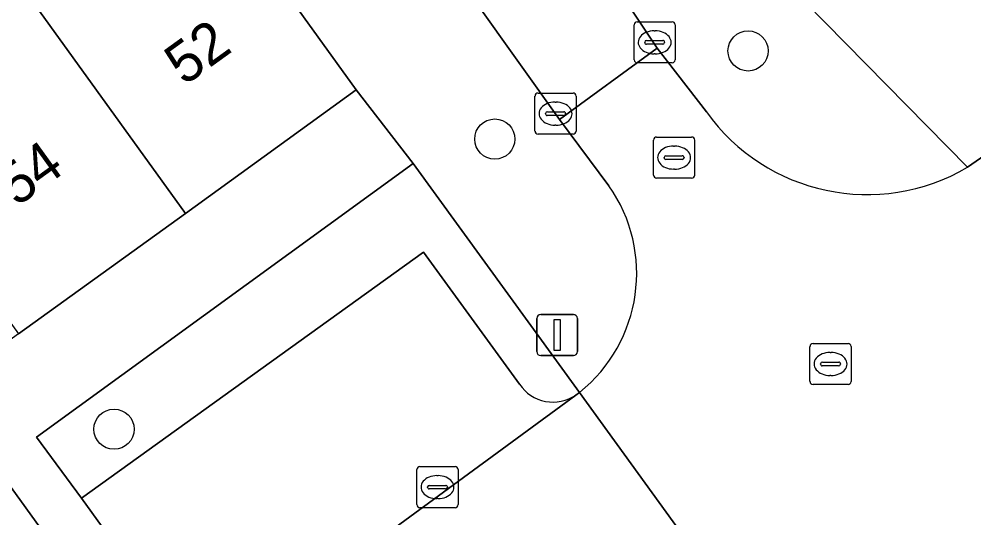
# Model space of a CAD drawing. Extents: x 159817 to 160765, y 380688 to 381638.
# Drawn here: x 159963.2 to 159986.43, y 381298.48 to 381310.61 of the extents above; entities that cross this region are included whole.
import ezdxf

# ---------------------------------------------------------------- set-up
doc = ezdxf.new("R2010")
doc.units = 0
for name, color, linetype in [('IMGEO_Boom', 7, 'Continuous'), ('IMGEO_Groenvoorziening', 7, 'Continuous'), ('IMGEO_Haag', 7, 'Continuous'), ('IMGEO_Kolk', 7, 'Continuous'), ('IMGEO_Lichtmast', 7, 'Continuous'), ('IMGEO_Pand', 7, 'Continuous'), ('IMGEO_Pand_nummerreeks', 7, 'Continuous'), ('IMGEO_Parkeervlak_open', 7, 'Continuous'), ('IMGEO_Rijbaan_lokaal_open', 7, 'Continuous'), ('IMGEO_Rioolput', 7, 'Continuous'), ('IMGEO_Voetpad_open', 7, 'Continuous')]:
    doc.layers.add(name, color=color, linetype=linetype)

msp = doc.modelspace()

# ---------------------------------------------------------------- linework, layer by layer
at = {"layer": 'IMGEO_Boom'}
for centre in [(159980.939, 381309.837), (159974.776, 381307.693), (159965.511, 381300.638)]:
    msp.add_circle(centre, 0.489, dxfattribs=at)
at = {"layer": 'IMGEO_Groenvoorziening'}
for points in [[(159976.746, 381301.467), (159976.837, 381301.534), (159972.788, 381307.097), (159963.625, 381300.445), (159964.722, 381298.96), (159973.039, 381304.942)], [(159973.039, 381304.942), (159975.38, 381301.732)], [(159957.49, 381293.728), (159963.72, 381298.234), (159962.646, 381299.714), (159946.408, 381287.912), (159947.492, 381286.426), (159956.615, 381293.074), (159959.604, 381288.981)]]:
    msp.add_lwpolyline(points, dxfattribs=at)
msp.add_arc((159976.195, 381302.28), 0.982, 213.9363, 304.106, dxfattribs=at)
at = {"layer": 'IMGEO_Haag'}
for points in [[(159976.746, 381301.467), (159976.837, 381301.534), (159972.788, 381307.097), (159963.625, 381300.445), (159964.722, 381298.96), (159973.039, 381304.942), (159975.38, 381301.732)], [(159957.49, 381293.728), (159963.72, 381298.234), (159962.646, 381299.714), (159946.408, 381287.912), (159947.492, 381286.426), (159956.615, 381293.074), (159959.604, 381288.981)]]:
    msp.add_lwpolyline(points, dxfattribs=at)
msp.add_arc((159976.195, 381302.28), 0.982, 213.9363, 304.106, dxfattribs=at)
at = {"layer": 'IMGEO_Kolk'}
for p, q in [((159978.24, 381310.546), (159979.092, 381310.546)), ((159978.165, 381309.62), (159978.165, 381310.472)), ((159978.653, 381310.326), (159978.678, 381310.326)), ((159979.166, 381310.472), (159979.166, 381309.62)), ((159978.467, 381310.089), (159978.865, 381310.089)), ((159978.424, 381310.04), (159978.424, 381310.052)), ((159978.862, 381310.003), (159978.464, 381310.003)), ((159978.908, 381310.052), (159978.908, 381310.04)), ((159978.676, 381309.766), (159978.651, 381309.766)), ((159979.092, 381309.546), (159978.24, 381309.546)), ((159975.754, 381307.886), (159975.754, 381308.738)), ((159975.829, 381308.812), (159976.681, 381308.812)), ((159976.755, 381308.738), (159976.755, 381307.886)), ((159976.242, 381308.592), (159976.267, 381308.592)), ((159976.013, 381308.306), (159976.013, 381308.318)), ((159976.451, 381308.269), (159976.053, 381308.269)), ((159976.056, 381308.355), (159976.454, 381308.355)), ((159976.497, 381308.318), (159976.497, 381308.306)), ((159976.265, 381308.032), (159976.24, 381308.032)), ((159976.681, 381307.812), (159975.829, 381307.812)), ((159972.881, 381298.804), (159972.881, 381299.656)), ((159972.956, 381299.73), (159973.808, 381299.73)), ((159973.882, 381299.656), (159973.882, 381298.804)), ((159973.369, 381299.51), (159973.394, 381299.51)), ((159973.14, 381299.224), (159973.14, 381299.236)), ((159973.578, 381299.187), (159973.18, 381299.187)), ((159973.183, 381299.273), (159973.581, 381299.273)), ((159973.624, 381299.236), (159973.624, 381299.224)), ((159973.392, 381298.95), (159973.367, 381298.95)), ((159973.808, 381298.73), (159972.956, 381298.73))]:
    msp.add_line(p, q, dxfattribs=at)
for points in [[(159978.24, 381310.546), (159979.092, 381310.546)], [(159978.165, 381309.62), (159978.165, 381310.472)], [(159979.166, 381310.472), (159979.166, 381309.62)], [(159979.092, 381309.546), (159978.24, 381309.546)], [(159975.754, 381307.886), (159975.754, 381308.738)], [(159975.829, 381308.812), (159976.681, 381308.812)], [(159976.755, 381308.738), (159976.755, 381307.886)], [(159976.681, 381307.812), (159975.829, 381307.812)], [(159972.881, 381298.804), (159972.881, 381299.656)], [(159972.956, 381299.73), (159973.808, 381299.73)], [(159973.882, 381299.656), (159973.882, 381298.804)], [(159973.808, 381298.73), (159972.956, 381298.73)]]:
    msp.add_lwpolyline(points, dxfattribs=at)
for centre, radius, start, end in [((159978.242, 381310.47), 0.0765, 91.552, 178.448), ((159978.242, 381310.47), 0.0765, 91.552, 178.448), ((159979.09, 381310.47), 0.0765, 1.552, 88.448), ((159979.09, 381310.47), 0.0765, 1.552, 88.448), ((159978.464, 381310.049), 0.0403, 85.8775, 175.7526), ((159978.869, 381310.051), 0.0386, 1.7309, 96.639), ((159978.461, 381310.039), 0.0366, 178.938, 274.7102), ((159978.865, 381310.046), 0.043, 264.8664, 352.4533), ((159978.242, 381309.622), 0.0765, 181.552, 268.448), ((159978.242, 381309.622), 0.0765, 181.552, 268.448), ((159979.09, 381309.622), 0.0765, 271.552, 358.448), ((159979.09, 381309.622), 0.0765, 271.552, 358.448), ((159975.831, 381308.736), 0.0765, 91.552, 178.448), ((159975.831, 381308.736), 0.0765, 91.552, 178.448), ((159976.679, 381308.736), 0.0765, 1.552, 88.448), ((159976.679, 381308.736), 0.0765, 1.552, 88.448), ((159976.053, 381308.315), 0.0403, 85.8775, 175.7526), ((159976.05, 381308.305), 0.0366, 178.938, 274.7102), ((159976.454, 381308.312), 0.043, 264.8664, 352.4533), ((159976.458, 381308.317), 0.0386, 1.7309, 96.639), ((159975.831, 381307.888), 0.0765, 181.552, 268.448), ((159975.831, 381307.888), 0.0765, 181.552, 268.448), ((159976.679, 381307.888), 0.0765, 271.552, 358.448), ((159976.679, 381307.888), 0.0765, 271.552, 358.448), ((159972.958, 381299.654), 0.0765, 91.552, 178.448), ((159972.958, 381299.654), 0.0765, 91.552, 178.448), ((159973.806, 381299.654), 0.0765, 1.552, 88.448), ((159973.806, 381299.654), 0.0765, 1.552, 88.448), ((159973.18, 381299.233), 0.0403, 85.8775, 175.7526), ((159973.177, 381299.223), 0.0366, 178.938, 274.7102), ((159973.581, 381299.23), 0.043, 264.8664, 352.4533), ((159973.585, 381299.235), 0.0386, 1.7309, 96.639), ((159972.958, 381298.806), 0.0765, 181.552, 268.448), ((159972.958, 381298.806), 0.0765, 181.552, 268.448), ((159973.806, 381298.806), 0.0765, 271.552, 358.448), ((159973.806, 381298.806), 0.0765, 271.552, 358.448)]:
    msp.add_arc(centre, radius, start, end, dxfattribs=at)
for centre, major_axis, ratio, start_param, end_param in [((159978.652, 381310.046), (-0.387, 0.002), 0.722429, 4.712389, 7.853982), ((159978.677, 381310.046), (-0.39, 0.002), 0.717154, 1.570796, 4.712389), ((159976.241, 381308.312), (-0.387, 0.002), 0.722429, 4.712389, 7.853982), ((159976.266, 381308.312), (-0.39, 0.002), 0.717154, 1.570796, 4.712389), ((159973.368, 381299.23), (-0.387, 0.002), 0.722429, 4.712389, 7.853982), ((159973.393, 381299.23), (-0.39, 0.002), 0.717154, 1.570796, 4.712389)]:
    msp.add_ellipse(centre, major_axis=major_axis, ratio=ratio, start_param=start_param, end_param=end_param, dxfattribs=at)
at = {"layer": 'IMGEO_Lichtmast'}
for p, q in [((159975.797, 381302.528), (159975.797, 381303.328)), ((159975.797, 381303.328), (159975.797, 381302.528)), ((159975.897, 381303.428), (159976.687, 381303.428)), ((159976.687, 381303.428), (159975.897, 381303.428)), ((159976.787, 381303.328), (159976.787, 381302.528)), ((159976.787, 381302.528), (159976.787, 381303.328)), ((159976.687, 381302.428), (159975.897, 381302.428)), ((159975.897, 381302.428), (159976.687, 381302.428))]:
    msp.add_line(p, q, dxfattribs=at)
msp.add_lwpolyline([(159976.217, 381303.303), (159976.367, 381303.303), (159976.367, 381302.553), (159976.217, 381302.553), (159976.217, 381303.303)], dxfattribs=at)
for centre, start, end in [((159975.897, 381303.328), 90, 180), ((159975.897, 381303.328), 90, 180), ((159976.687, 381303.328), 0, 90), ((159976.687, 381303.328), 360, 90), ((159975.897, 381302.528), 180, 270), ((159975.897, 381302.528), 180, 270), ((159976.687, 381302.528), 270, 0), ((159976.687, 381302.528), 270, 0)]:
    msp.add_arc(centre, 0.1, start, end, dxfattribs=at)
at = {"layer": 'IMGEO_Pand'}
for points in [[(159967.247, 381305.886), (159971.406, 381308.887), (159965.25, 381317.425), (159962.974, 381315.784), (159961.504, 381317.824), (159959.614, 381316.461)], [(159967.247, 381305.886), (159959.614, 381316.461), (159957.821, 381315.169), (159959.328, 381313.078), (159957.059, 381311.442), (159958.797, 381309.033), (159963.185, 381302.954)]]:
    msp.add_lwpolyline(points, close=True, dxfattribs=at)
at = {"layer": 'IMGEO_Parkeervlak_open'}
msp.add_lwpolyline([(159975.38, 381301.732), (159973.039, 381304.942), (159964.722, 381298.96), (159967.693, 381294.838), (159976.746, 381301.467)], dxfattribs=at)
msp.add_arc((159976.195, 381302.28), 0.982, 213.9363, 304.106, dxfattribs=at)
at = {"layer": 'IMGEO_Rijbaan_lokaal_open'}
for points in [[(159976.349, 381308.172), (159978.729, 381309.905), (159977.95, 381311.079), (159948.598, 381351.357), (159948.297, 381351.788), (159948.232, 381351.877), (159942.983, 381359.055), (159942.736, 381359.408), (159940.386, 381357.691), (159940.578, 381357.426), (159950.269, 381344.107), (159950.885, 381343.28), (159960.657, 381329.81), (159961.231, 381329.017), (159973.21, 381312.558), (159974.328, 381310.996)], [(159980.223, 381296.539), (159980.375, 381296.648), (159976.837, 381301.534), (159976.746, 381301.467), (159967.693, 381294.838), (159966.715, 381294.128), (159959.604, 381288.981), (159963.13, 381284.119), (159963.218, 381284.184), (159970.234, 381289.284), (159971.194, 381289.99)]]:
    msp.add_lwpolyline(points, close=True, dxfattribs=at)
for points in [[(159979.924, 381308.353), (159978.729, 381309.905), (159976.349, 381308.172), (159977.553, 381306.556)], [(159988.478, 381303.94), (159989.9, 381304.979), (159987.706, 381308.002), (159986.277, 381307.01)], [(159976.837, 381301.534), (159980.375, 381296.648)]]:
    msp.add_lwpolyline(points, dxfattribs=at)
for centre, radius, start, end in [((159983.836, 381311.159), 4.814, 215.6508, 300.4764), ((159974.528, 381304.425), 3.7, 308.6139, 35.1578)]:
    msp.add_arc(centre, radius, start, end, dxfattribs=at)
at = {"layer": 'IMGEO_Rioolput'}
for p, q in [((159978.713, 381307.743), (159979.565, 381307.743)), ((159978.638, 381306.817), (159978.638, 381307.669)), ((159979.126, 381307.523), (159979.151, 381307.523)), ((159979.639, 381307.669), (159979.639, 381306.817)), ((159978.94, 381307.286), (159979.338, 381307.286)), ((159978.897, 381307.237), (159978.897, 381307.249)), ((159979.335, 381307.2), (159978.937, 381307.2)), ((159979.381, 381307.249), (159979.381, 381307.237)), ((159979.149, 381306.963), (159979.124, 381306.963)), ((159979.565, 381306.743), (159978.713, 381306.743)), ((159982.445, 381301.798), (159982.445, 381302.65)), ((159982.52, 381302.724), (159983.372, 381302.724)), ((159983.446, 381302.65), (159983.446, 381301.798)), ((159982.933, 381302.504), (159982.958, 381302.504)), ((159982.704, 381302.218), (159982.704, 381302.23)), ((159983.142, 381302.181), (159982.744, 381302.181)), ((159982.747, 381302.267), (159983.145, 381302.267)), ((159983.188, 381302.23), (159983.188, 381302.218)), ((159982.956, 381301.944), (159982.931, 381301.944)), ((159983.372, 381301.724), (159982.52, 381301.724))]:
    msp.add_line(p, q, dxfattribs=at)
for points in [[(159978.713, 381307.743), (159979.565, 381307.743)], [(159978.638, 381306.817), (159978.638, 381307.669)], [(159979.639, 381307.669), (159979.639, 381306.817)], [(159979.565, 381306.743), (159978.713, 381306.743)], [(159982.445, 381301.798), (159982.445, 381302.65)], [(159982.52, 381302.724), (159983.372, 381302.724)], [(159983.446, 381302.65), (159983.446, 381301.798)], [(159983.372, 381301.724), (159982.52, 381301.724)]]:
    msp.add_lwpolyline(points, dxfattribs=at)
for centre, radius, start, end in [((159978.715, 381307.667), 0.0765, 91.552, 178.448), ((159978.715, 381307.667), 0.0765, 91.552, 178.448), ((159979.563, 381307.667), 0.0765, 1.552, 88.448), ((159979.563, 381307.667), 0.0765, 1.552, 88.448), ((159978.937, 381307.246), 0.0403, 85.8775, 175.7526), ((159979.342, 381307.248), 0.0386, 1.7309, 96.639), ((159978.934, 381307.236), 0.0366, 178.938, 274.7102), ((159979.338, 381307.243), 0.043, 264.8664, 352.4533), ((159978.715, 381306.819), 0.0765, 181.552, 268.448), ((159978.715, 381306.819), 0.0765, 181.552, 268.448), ((159979.563, 381306.819), 0.0765, 271.552, 358.448), ((159979.563, 381306.819), 0.0765, 271.552, 358.448), ((159982.522, 381302.648), 0.0765, 91.552, 178.448), ((159982.522, 381302.648), 0.0765, 91.552, 178.448), ((159983.37, 381302.648), 0.0765, 1.552, 88.448), ((159983.37, 381302.648), 0.0765, 1.552, 88.448), ((159982.744, 381302.227), 0.0403, 85.8775, 175.7526), ((159982.741, 381302.217), 0.0366, 178.938, 274.7102), ((159983.145, 381302.224), 0.043, 264.8664, 352.4533), ((159983.149, 381302.229), 0.0386, 1.7309, 96.639), ((159982.522, 381301.8), 0.0765, 181.552, 268.448), ((159982.522, 381301.8), 0.0765, 181.552, 268.448), ((159983.37, 381301.8), 0.0765, 271.552, 358.448), ((159983.37, 381301.8), 0.0765, 271.552, 358.448)]:
    msp.add_arc(centre, radius, start, end, dxfattribs=at)
for centre, major_axis, ratio, start_param, end_param in [((159979.125, 381307.243), (-0.387, 0.002), 0.722429, 4.712389, 7.853982), ((159979.15, 381307.243), (-0.39, 0.002), 0.717154, 1.570796, 4.712389), ((159982.932, 381302.224), (-0.387, 0.002), 0.722429, 4.712389, 7.853982), ((159982.957, 381302.224), (-0.39, 0.002), 0.717154, 1.570796, 4.712389)]:
    msp.add_ellipse(centre, major_axis=major_axis, ratio=ratio, start_param=start_param, end_param=end_param, dxfattribs=at)
at = {"layer": 'IMGEO_Voetpad_open'}
for points in [[(159937.01, 381356.62), (159937.488, 381355.703), (159940.981, 381349.218), (159942.045, 381349.029), (159947.377, 381341.706), (159948.307, 381340.429), (159951.211, 381336.506), (159954.044, 381332.678), (159956.877, 381328.851), (159959.782, 381324.927), (159960.581, 381323.831), (159965.25, 381317.425), (159971.406, 381308.887), (159972.788, 381307.097), (159976.837, 381301.534)], [(159986.277, 381307.01), (159982.331, 381311.019), (159979.645, 381314.832), (159977.548, 381317.809), (159974.762, 381321.597), (159973.461, 381323.366), (159971.698, 381325.763), (159971.677, 381325.792), (159970.815, 381326.937), (159967.892, 381330.909), (159965.178, 381334.598)], [(159977.553, 381306.556), (159976.349, 381308.172), (159974.328, 381310.996), (159973.21, 381312.558)], [(159977.95, 381311.079), (159978.729, 381309.905), (159979.924, 381308.353)], [(159982.331, 381311.019), (159986.277, 381307.01), (159987.706, 381308.002), (159988.276, 381308.413)], [(159928.168, 381274.619), (159943.953, 381286.112), (159946.408, 381287.912), (159962.646, 381299.714), (159963.72, 381298.234), (159966.715, 381294.128), (159967.693, 381294.838), (159964.722, 381298.96), (159963.625, 381300.445), (159972.788, 381307.097), (159971.406, 381308.887), (159967.247, 381305.886), (159963.185, 381302.954), (159959.123, 381300.023), (159955.06, 381297.091), (159950.998, 381294.159), (159946.936, 381291.228), (159942.874, 381288.296), (159938.812, 381285.365), (159934.75, 381282.433), (159930.688, 381279.502), (159926.625, 381276.57)]]:
    msp.add_lwpolyline(points, dxfattribs=at)
for centre, radius, start, end in [((159983.836, 381311.159), 4.814, 215.6508, 300.4764), ((159974.528, 381304.425), 3.7, 308.6139, 35.1578)]:
    msp.add_arc(centre, radius, start, end, dxfattribs=at)

# ---------------------------------------------------------------- texts
at = {"layer": 'IMGEO_Pand_nummerreeks'}
for s, p in [('52', (159967.22, 381308.974)), ('54', (159963.143, 381306.032))]:
    msp.add_text(s, height=1, rotation=35.8169, dxfattribs=at).set_placement(p)

doc.saveas('drawing.dxf')
